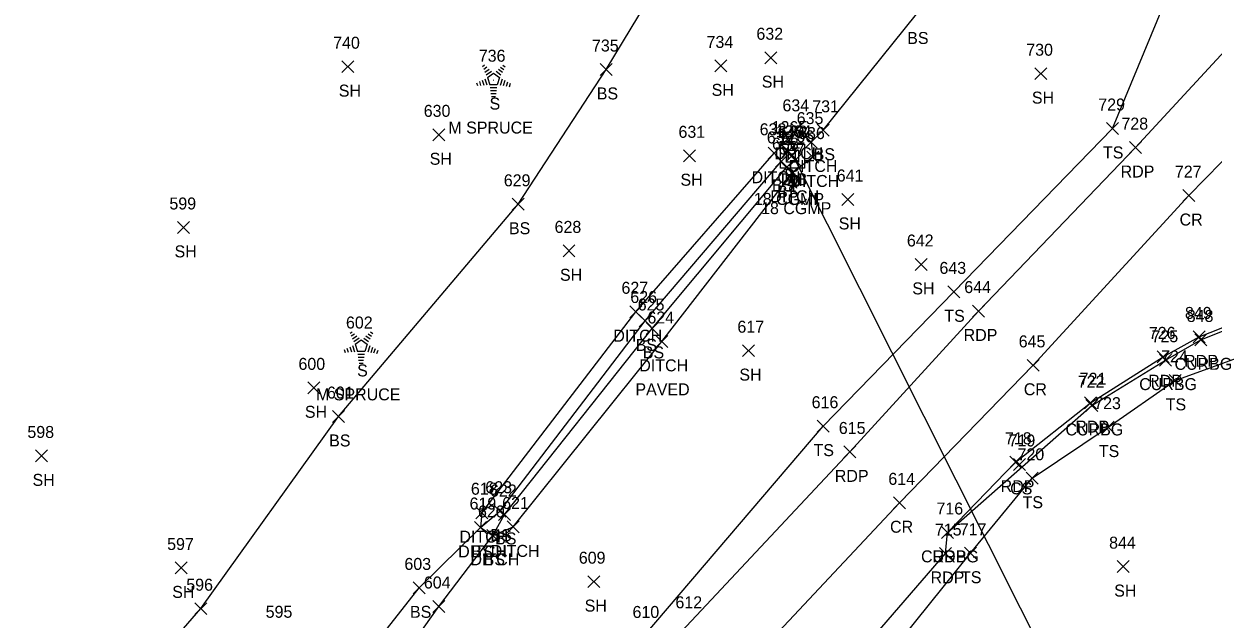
# Model space of a CAD drawing. Extents: x 1688195 to 1692013, y 424605 to 441234.
# Drawn here: x 1691519.2 to 1691718.1, y 439174.5 to 439274 of the extents above; entities that cross this region are included whole.
import ezdxf

# ---------------------------------------------------------------- set-up
doc = ezdxf.new("R2010")
doc.units = 0
for name, color, linetype in [('D_A', 7, 'Continuous'), ('D_C', 7, 'Continuous'), ('D_I', 7, 'Continuous'), ('D_TIC', 7, 'Continuous'), ('DCP', 7, 'Continuous'), ('DD', 7, 'Continuous'), ('DS', 7, 'Continuous'), ('L_A', 7, 'Continuous'), ('L_C', 7, 'Continuous'), ('L_I', 7, 'Continuous'), ('L_TIC', 7, 'Continuous'), ('LELB', 7, 'Continuous'), ('LTC', 7, 'Continuous'), ('P_A', 7, 'Continuous'), ('P_I', 7, 'Continuous'), ('P_TIC', 7, 'Continuous'), ('PET', 7, 'Continuous'), ('PRC', 7, 'Continuous'), ('R_A', 7, 'Continuous'), ('R_I', 7, 'Continuous'), ('R_TIC', 7, 'Continuous'), ('RC', 7, 'Continuous')]:
    doc.layers.add(name, color=color, linetype=linetype)

msp = doc.modelspace()

# ---------------------------------------------------------------- linework, layer by layer
at = {"layer": 'D_TIC'}
for points in [[(1691647.47, 439255.34), (1691649.47, 439257.34)], [(1691649.47, 439255.34), (1691647.47, 439257.34)], [(1691649.85, 439253.21), (1691651.85, 439255.21)], [(1691651.85, 439253.21), (1691649.85, 439255.21)], [(1691643.66, 439251.34), (1691645.66, 439253.34)], [(1691645.66, 439251.34), (1691643.66, 439253.34)], [(1691645.99, 439251.71), (1691647.99, 439253.71)], [(1691647.99, 439251.71), (1691645.99, 439253.71)], [(1691646.66, 439250.99), (1691648.66, 439252.99)], [(1691648.66, 439250.99), (1691646.66, 439252.99)], [(1691647.19, 439250.17), (1691649.19, 439252.17)], [(1691649.19, 439250.17), (1691647.19, 439252.17)], [(1691650.14, 439250.71), (1691652.14, 439252.71)], [(1691652.14, 439250.71), (1691650.14, 439252.71)], [(1691646.8, 439248.15), (1691648.8, 439250.15)], [(1691648.8, 439248.15), (1691646.8, 439250.15)], [(1691646.8, 439248.15), (1691648.8, 439250.15)], [(1691648.8, 439248.15), (1691646.8, 439250.15)], [(1691620.56, 439224.87), (1691622.56, 439226.87)], [(1691622.56, 439224.87), (1691620.56, 439226.87)], [(1691624.9, 439219.91), (1691626.9, 439221.91)], [(1691626.9, 439219.91), (1691624.9, 439221.91)], [(1691594.83, 439191.31), (1691596.83, 439193.31)], [(1691596.83, 439191.31), (1691594.83, 439193.31)], [(1691594.83, 439191.31), (1691596.83, 439193.31)], [(1691596.83, 439191.31), (1691594.83, 439193.31)], [(1691594.61, 439188.84), (1691596.61, 439190.84)], [(1691596.61, 439188.84), (1691594.61, 439190.84)], [(1691596.67, 439187.52), (1691598.67, 439189.52)], [(1691598.67, 439187.52), (1691596.67, 439189.52)], [(1691600.05, 439188.93), (1691602.05, 439190.93)], [(1691602.05, 439188.93), (1691600.05, 439190.93)]]:
    msp.add_lwpolyline(points, dxfattribs=at)
at = {"layer": 'DCP'}
msp.add_lwpolyline([(1691648.19, 439251.17), (1691707.28, 439133.69)], dxfattribs=at)
at = {"layer": 'DD'}
for points in [[(1691595.83, 439192.31), (1691621.56, 439225.87), (1691644.66, 439252.34), (1691648.47, 439256.34), (1691650.85, 439254.21), (1691651.14, 439251.71), (1691647.8, 439249.15)], [(1691595.83, 439192.31), (1691595.61, 439189.84), (1691597.67, 439188.52), (1691601.05, 439189.93), (1691625.9, 439220.91), (1691647.8, 439249.15)]]:
    msp.add_lwpolyline(points, dxfattribs=at)
at = {"layer": 'DS'}
for p, q in [((1691645.74, 439253.87), (1691649.74, 439253.87)), ((1691645.74, 439249.87), (1691645.74, 439253.87)), ((1691646.74, 439250.87), (1691646.74, 439252.87)), ((1691646.74, 439252.87), (1691648.74, 439252.87)), ((1691648.74, 439252.87), (1691648.74, 439250.87)), ((1691649.74, 439253.87), (1691649.74, 439249.87)), ((1691648.74, 439250.87), (1691646.74, 439250.87)), ((1691647.74, 439251.87), (1691647.74, 439251.87)), ((1691647.74, 439251.87), (1691647.74, 439251.87)), ((1691649.74, 439249.87), (1691645.74, 439249.87))]:
    msp.add_line(p, q, dxfattribs=at)
at = {"layer": 'L_TIC'}
for points in [[(1691643.12, 439267.3), (1691645.12, 439269.3)], [(1691645.12, 439267.3), (1691643.12, 439269.3)], [(1691572.41, 439265.8), (1691574.41, 439267.8)], [(1691574.41, 439265.8), (1691572.41, 439267.8)], [(1691615.58, 439265.33), (1691617.58, 439267.33)], [(1691617.58, 439265.33), (1691615.58, 439267.33)], [(1691634.74, 439265.93), (1691636.74, 439267.93)], [(1691636.74, 439265.93), (1691634.74, 439267.93)], [(1691688.26, 439264.63), (1691690.26, 439266.63)], [(1691690.26, 439264.63), (1691688.26, 439266.63)], [(1691651.84, 439255.18), (1691653.84, 439257.18)], [(1691653.84, 439255.18), (1691651.84, 439257.18)], [(1691700.22, 439255.48), (1691702.22, 439257.48)], [(1691702.22, 439255.48), (1691700.22, 439257.48)], [(1691587.6, 439254.42), (1691589.6, 439256.42)], [(1691589.6, 439254.42), (1691587.6, 439256.42)], [(1691629.52, 439250.92), (1691631.52, 439252.92)], [(1691631.52, 439250.92), (1691629.52, 439252.92)], [(1691644.87, 439249.99), (1691646.87, 439251.99)], [(1691646.87, 439249.99), (1691644.87, 439251.99)], [(1691644.87, 439249.99), (1691646.87, 439251.99)], [(1691646.87, 439249.99), (1691644.87, 439251.99)], [(1691645.72, 439248.94), (1691647.72, 439250.94)], [(1691647.72, 439248.94), (1691645.72, 439250.94)], [(1691655.97, 439243.62), (1691657.97, 439245.62)], [(1691657.97, 439243.62), (1691655.97, 439245.62)], [(1691600.9, 439242.82), (1691602.9, 439244.82)], [(1691602.9, 439242.82), (1691600.9, 439244.82)], [(1691544.96, 439238.95), (1691546.96, 439240.95)], [(1691546.96, 439238.95), (1691544.96, 439240.95)], [(1691609.38, 439235.04), (1691611.38, 439237.04)], [(1691611.38, 439235.04), (1691609.38, 439237.04)], [(1691668.27, 439232.77), (1691670.27, 439234.77)], [(1691670.27, 439232.77), (1691668.27, 439234.77)], [(1691673.71, 439228.19), (1691675.71, 439230.19)], [(1691675.71, 439228.19), (1691673.71, 439230.19)], [(1691622.09, 439223.33), (1691624.09, 439225.33)], [(1691624.09, 439223.33), (1691622.09, 439225.33)], [(1691623.28, 439222.08), (1691625.28, 439224.08)], [(1691625.28, 439222.08), (1691623.28, 439224.08)], [(1691639.37, 439218.37), (1691641.37, 439220.37)], [(1691641.37, 439218.37), (1691639.37, 439220.37)], [(1691710.71, 439213.4), (1691712.71, 439215.4)], [(1691712.71, 439213.4), (1691710.71, 439215.4)], [(1691566.74, 439212.16), (1691568.74, 439214.16)], [(1691568.74, 439212.16), (1691566.74, 439214.16)], [(1691570.85, 439207.37), (1691572.85, 439209.37)], [(1691572.85, 439207.37), (1691570.85, 439209.37)], [(1691651.84, 439205.76), (1691653.84, 439207.76)], [(1691653.84, 439205.76), (1691651.84, 439207.76)], [(1691699.53, 439205.6), (1691701.53, 439207.6)], [(1691701.53, 439205.6), (1691699.53, 439207.6)], [(1691521.22, 439200.79), (1691523.22, 439202.79)], [(1691523.22, 439200.79), (1691521.22, 439202.79)], [(1691684.67, 439199.37), (1691686.67, 439201.37)], [(1691686.67, 439199.37), (1691684.67, 439201.37)], [(1691686.79, 439197.06), (1691688.79, 439199.06)], [(1691688.79, 439197.06), (1691686.79, 439199.06)], [(1691597.8, 439191.56), (1691599.8, 439193.56)], [(1691599.8, 439191.56), (1691597.8, 439193.56)], [(1691598.59, 439191.01), (1691600.59, 439193.01)], [(1691600.59, 439191.01), (1691598.59, 439193.01)], [(1691594.61, 439188.84), (1691596.61, 439190.84)], [(1691596.61, 439188.84), (1691594.61, 439190.84)], [(1691596.67, 439187.52), (1691598.67, 439189.52)], [(1691598.67, 439187.52), (1691596.67, 439189.52)], [(1691676.5, 439184.53), (1691678.5, 439186.53)], [(1691678.5, 439184.53), (1691676.5, 439186.53)], [(1691544.57, 439182.08), (1691546.57, 439184.08)], [(1691546.57, 439182.08), (1691544.57, 439184.08)], [(1691702.02, 439182.3), (1691704.02, 439184.3)], [(1691704.02, 439182.3), (1691702.02, 439184.3)], [(1691613.52, 439179.79), (1691615.52, 439181.79)], [(1691615.52, 439179.79), (1691613.52, 439181.79)], [(1691584.36, 439178.75), (1691586.36, 439180.75)], [(1691586.36, 439178.75), (1691584.36, 439180.75)], [(1691547.83, 439175.28), (1691549.83, 439177.28)], [(1691549.83, 439175.28), (1691547.83, 439177.28)], [(1691587.61, 439175.65), (1691589.61, 439177.65)], [(1691589.61, 439175.65), (1691587.61, 439177.65)]]:
    msp.add_lwpolyline(points, dxfattribs=at)
at = {"layer": 'LELB'}
for points in [[(1691372.73, 438902.64), (1691398.57, 438929.63), (1691421.61, 438954.81), (1691450.5, 438984.08), (1691477.46, 439013.34), (1691508.26, 439046.52), (1691540.85, 439082.44), (1691568.31, 439110.72), (1691593.69, 439141.21), (1691622.93, 439171.73), (1691652.84, 439206.76), (1691674.71, 439229.19), (1691701.22, 439256.48), (1691710.89, 439279.75), (1691723.95, 439307.99), (1691712.17, 439332.07), (1691693.94, 439358.26), (1691684, 439373.02)], [(1691525.69, 439149.58), (1691548.83, 439176.28), (1691571.85, 439208.37), (1691601.9, 439243.82), (1691616.58, 439266.33), (1691638.43, 439302.46), (1691663.4, 439335.24), (1691663.94, 439360.51)], [(1691652.84, 439256.18), (1691668.47, 439275.59), (1691689.85, 439296.94)], [(1691358.65, 438915.95), (1691383.88, 438942.54), (1691406.19, 438968.83), (1691432.09, 439000.43), (1691458.78, 439030.79), (1691488.91, 439063.66), (1691516.55, 439102.83), (1691546.52, 439127.21), (1691571.44, 439162.09), (1691585.36, 439179.75), (1691595.61, 439189.84), (1691598.8, 439192.56), (1691623.09, 439224.33), (1691645.87, 439250.99)], [(1691362.51, 438912.64), (1691386.93, 438940.67), (1691409.23, 438967.09), (1691436.47, 438996.99), (1691463, 439026.81), (1691492.43, 439060.22), (1691523.16, 439097.82), (1691549.35, 439125.66), (1691575.52, 439158.24), (1691588.61, 439176.65), (1691597.67, 439188.52), (1691599.59, 439192.01), (1691624.28, 439223.08), (1691646.72, 439249.94), (1691645.87, 439250.99)], [(1691494.97, 438989.23), (1691529.39, 439026.47), (1691563.11, 439061.46), (1691592.32, 439093.25), (1691622.45, 439123.57), (1691640.28, 439144.55), (1691642.63, 439146.18), (1691644.54, 439148.64), (1691657.14, 439160.25), (1691677.5, 439185.53), (1691687.79, 439198.06), (1691700.53, 439206.6), (1691711.71, 439214.4), (1691729.93, 439221), (1691765.22, 439228.65), (1691785.8, 439230.06)]]:
    msp.add_lwpolyline(points, dxfattribs=at)
at = {"layer": 'LTC'}
for p, q in [((1691595.91, 439266.83), (1691596.27, 439267.09)), ((1691596.12, 439266.37), (1691596.65, 439266.75)), ((1691598.94, 439266.73), (1691599.49, 439266.33)), ((1691599.31, 439267.07), (1691599.73, 439266.77)), ((1691596.31, 439264.76), (1691596.64, 439263.74)), ((1691596.33, 439265.9), (1691597.03, 439266.41)), ((1691596.54, 439265.44), (1691597.42, 439266.07)), ((1691596.77, 439264.98), (1691597.78, 439265.72)), ((1691596.77, 439264.98), (1691597.15, 439263.79)), ((1691597.78, 439265.72), (1691598.77, 439264.99)), ((1691598.2, 439266.03), (1691599.01, 439265.44)), ((1691598.77, 439264.99), (1691598.38, 439263.79)), ((1691598.57, 439266.38), (1691599.25, 439265.88)), ((1691599.21, 439264.72), (1691598.87, 439263.68)), ((1691594.94, 439264.11), (1691595.1, 439263.65)), ((1691595.4, 439264.33), (1691595.61, 439263.68)), ((1691595.86, 439264.55), (1691596.13, 439263.71)), ((1691598.38, 439263.79), (1691597.15, 439263.79)), ((1691598.34, 439263.29), (1691597.2, 439263.29)), ((1691598.26, 439262.79), (1691597.27, 439262.79)), ((1691599.66, 439264.47), (1691599.37, 439263.59)), ((1691600.1, 439264.22), (1691599.86, 439263.49)), ((1691600.54, 439263.97), (1691600.36, 439263.4)), ((1691598.18, 439262.29), (1691597.34, 439262.29)), ((1691598.09, 439261.79), (1691597.42, 439261.79)), ((1691573.78, 439222.28), (1691574.14, 439222.54)), ((1691573.99, 439221.82), (1691574.52, 439222.2)), ((1691574.2, 439221.35), (1691574.9, 439221.86)), ((1691574.41, 439220.88), (1691575.29, 439221.52)), ((1691574.63, 439220.43), (1691575.65, 439221.16)), ((1691575.65, 439221.16), (1691576.64, 439220.44)), ((1691576.07, 439221.48), (1691576.88, 439220.89)), ((1691576.44, 439221.82), (1691577.12, 439221.33)), ((1691576.81, 439222.17), (1691577.36, 439221.77)), ((1691577.18, 439222.52), (1691577.6, 439222.22)), ((1691572.81, 439219.56), (1691572.97, 439219.09)), ((1691573.27, 439219.78), (1691573.48, 439219.12)), ((1691573.72, 439219.99), (1691574, 439219.16)), ((1691574.18, 439220.21), (1691574.51, 439219.19)), ((1691574.63, 439220.43), (1691575.02, 439219.24)), ((1691576.25, 439219.24), (1691575.02, 439219.24)), ((1691576.64, 439220.44), (1691576.25, 439219.24)), ((1691577.08, 439220.17), (1691576.74, 439219.13)), ((1691577.52, 439219.92), (1691577.24, 439219.03)), ((1691577.97, 439219.67), (1691577.73, 439218.94)), ((1691578.41, 439219.42), (1691578.23, 439218.84)), ((1691576.21, 439218.74), (1691575.07, 439218.74)), ((1691576.13, 439218.24), (1691575.14, 439218.24)), ((1691576.05, 439217.74), (1691575.21, 439217.74)), ((1691575.96, 439217.24), (1691575.29, 439217.24))]:
    msp.add_line(p, q, dxfattribs=at)
at = {"layer": 'P_TIC'}
for points in [[(1691704.09, 439252.29), (1691706.09, 439254.29)], [(1691706.09, 439252.29), (1691704.09, 439254.29)], [(1691713.01, 439244.27), (1691715.01, 439246.27)], [(1691715.01, 439244.27), (1691713.01, 439246.27)], [(1691677.85, 439224.99), (1691679.85, 439226.99)], [(1691679.85, 439224.99), (1691677.85, 439226.99)], [(1691714.71, 439220.67), (1691716.71, 439222.67)], [(1691716.71, 439220.67), (1691714.71, 439222.67)], [(1691708.71, 439217.34), (1691710.71, 439219.34)], [(1691710.71, 439217.34), (1691708.71, 439219.34)], [(1691686.96, 439215.92), (1691688.96, 439217.92)], [(1691688.96, 439215.92), (1691686.96, 439217.92)], [(1691696.53, 439209.68), (1691698.53, 439211.68)], [(1691698.53, 439209.68), (1691696.53, 439211.68)], [(1691656.32, 439201.46), (1691658.32, 439203.46)], [(1691658.32, 439201.46), (1691656.32, 439203.46)], [(1691684.04, 439199.74), (1691686.04, 439201.74)], [(1691686.04, 439199.74), (1691684.04, 439201.74)], [(1691664.6, 439192.96), (1691666.6, 439194.96)], [(1691666.6, 439192.96), (1691664.6, 439194.96)], [(1691672.65, 439188.01), (1691674.65, 439190.01)], [(1691674.65, 439188.01), (1691672.65, 439190.01)], [(1691672.33, 439184.49), (1691674.33, 439186.49)], [(1691674.33, 439184.49), (1691672.33, 439186.49)]]:
    msp.add_lwpolyline(points, dxfattribs=at)
at = {"layer": 'PET'}
for points in [[(1691375.46, 438899.9), (1691401.5, 438927.23), (1691424.19, 438951.44), (1691479.53, 439011.25), (1691510.32, 439044.28), (1691543.27, 439079.53), (1691570.24, 439108.89), (1691596.97, 439137.86), (1691630.02, 439173.34), (1691657.32, 439202.46), (1691678.85, 439225.99), (1691705.09, 439253.29), (1691720.65, 439270.18), (1691741.75, 439292.31), (1691750.04, 439301.33), (1691750.82, 439305.81), (1691750.97, 439309.53)], [(1691527.98, 439028.02), (1691561.01, 439063.43), (1691590.68, 439095.16), (1691619.98, 439126.48), (1691638.57, 439146.32), (1691653.83, 439162.94), (1691673.33, 439185.49), (1691673.65, 439189.01), (1691685.04, 439200.74), (1691697.53, 439210.68), (1691709.71, 439218.34), (1691715.71, 439221.67), (1691737.08, 439230.06)]]:
    msp.add_lwpolyline(points, dxfattribs=at)
at = {"layer": 'PRC'}
msp.add_lwpolyline([(1691383.45, 438891.46), (1691410.11, 438918.45), (1691432.71, 438943.44), (1691460.69, 438973.59), (1691487.77, 439002.58), (1691519.39, 439036.11), (1691551.83, 439070.88), (1691579.21, 439100.29), (1691605.82, 439129.37), (1691637.88, 439164.38), (1691665.6, 439193.96), (1691687.96, 439216.92), (1691714.01, 439245.27), (1691730.35, 439261.96), (1691750.53, 439284.62), (1691763.38, 439297.71)], dxfattribs=at)
at = {"layer": 'R_TIC'}
for points in [[(1691715, 439220.17), (1691717, 439222.17)], [(1691717, 439220.17), (1691715, 439222.17)], [(1691709.11, 439216.78), (1691711.11, 439218.78)], [(1691711.11, 439216.78), (1691709.11, 439218.78)], [(1691696.78, 439209.21), (1691698.78, 439211.21)], [(1691698.78, 439209.21), (1691696.78, 439211.21)], [(1691672.65, 439188.01), (1691674.65, 439190.01)], [(1691674.65, 439188.01), (1691672.65, 439190.01)]]:
    msp.add_lwpolyline(points, dxfattribs=at)
at = {"layer": 'RC'}
msp.add_lwpolyline([(1691673.65, 439189.01), (1691697.78, 439210.21), (1691710.11, 439217.78), (1691716, 439221.17), (1691737.36, 439229.74), (1691750.14, 439233.54), (1691763.41, 439236.01), (1691779.91, 439237.57), (1691792.75, 439237.29), (1691801.61, 439236.31), (1691804.32, 439236.19)], dxfattribs=at)

# ---------------------------------------------------------------- texts
at = {"layer": 'D_A'}
for s, p in [('DITCH', (1691644.71, 439251.34)), ('DITCH', (1691647.08, 439249.21)), ('DITCH', (1691640.9, 439247.34)), ('DIB', (1691645.77, 439246.99)), ('P', (1691646.36, 439247.71)), ('DI', (1691646.8, 439246.87)), ('DITCH', (1691647.38, 439246.71)), ('P', (1691647.57, 439246.17)), ('DITCH', (1691644.03, 439244.15)), ('DITCH', (1691644.03, 439244.15)), ('DITCH', (1691617.79, 439220.87)), ('DITCH', (1691622.13, 439215.91)), ('DITCH', (1691592.06, 439187.31)), ('DITCH', (1691592.06, 439187.31)), ('DITCH', (1691591.85, 439184.84)), ('DITCH', (1691593.91, 439183.52)), ('DITCH', (1691597.29, 439184.93))]:
    msp.add_text(s, height=2, dxfattribs=at).set_placement(p)
at = {"layer": 'D_C'}
for s, p in [('18 CGMP', (1691641.28, 439243.71)), ('18 CGMP', (1691642.49, 439242.17)), ('PAVED', (1691621.48, 439211.91))]:
    msp.add_text(s, height=2, dxfattribs=at).set_placement(p)
at = {"layer": 'D_I'}
for s, p in [('634', (1691646.06, 439259.34)), ('635', (1691648.44, 439257.21)), ('633', (1691642.25, 439255.34)), ('1265', (1691644.25, 439255.71)), ('1264', (1691644.92, 439254.99)), ('640', (1691645.25, 439254.87)), ('1266', (1691645.4, 439254.17)), ('636', (1691648.68, 439254.71)), ('637', (1691645.39, 439252.15)), ('637', (1691645.39, 439252.15)), ('627', (1691619.15, 439228.87)), ('624', (1691623.49, 439223.91)), ('618', (1691593.98, 439195.31)), ('618', (1691593.98, 439195.31)), ('619', (1691593.76, 439192.84)), ('620', (1691595.17, 439191.52)), ('621', (1691599.21, 439192.93))]:
    msp.add_text(s, height=2, dxfattribs=at).set_placement(p)
at = {"layer": 'L_A'}
for s, p in [('BS', (1691666.91, 439270.59)), ('SH', (1691642.6, 439263.3)), ('SH', (1691571.9, 439261.8)), ('BS', (1691615.02, 439261.33)), ('SH', (1691634.22, 439261.93)), ('S', (1691597.1, 439259.63)), ('SH', (1691687.75, 439260.63)), ('BS', (1691651.28, 439251.18)), ('TS', (1691699.63, 439251.48)), ('SH', (1691587.09, 439250.42)), ('SH', (1691629.01, 439246.92)), ('BS', (1691644.31, 439245.99)), ('BS', (1691644.31, 439245.99)), ('BS', (1691645.16, 439244.94)), ('SH', (1691655.46, 439239.62)), ('BS', (1691600.34, 439238.82)), ('SH', (1691544.45, 439234.95)), ('SH', (1691608.87, 439231.04)), ('SH', (1691667.76, 439228.77)), ('TS', (1691673.12, 439224.19)), ('BS', (1691621.53, 439219.33)), ('BS', (1691622.72, 439218.08)), ('S', (1691574.97, 439215.07)), ('SH', (1691638.86, 439214.37)), ('TS', (1691710.12, 439209.4)), ('SH', (1691566.23, 439208.16)), ('BS', (1691570.29, 439203.37)), ('TS', (1691651.25, 439201.76)), ('TS', (1691698.94, 439201.6)), ('SH', (1691520.71, 439196.79)), ('CS', (1691684.11, 439195.37)), ('TS', (1691686.2, 439193.06)), ('BS', (1691597.24, 439187.56)), ('BS', (1691598.03, 439187.01)), ('BS', (1691594.06, 439184.84)), ('BS', (1691596.11, 439183.52)), ('TS', (1691675.9, 439180.53)), ('SH', (1691544.06, 439178.08)), ('SH', (1691701.51, 439178.3)), ('SH', (1691613, 439175.79)), ('BS', (1691583.8, 439174.75))]:
    msp.add_text(s, height=2, dxfattribs=at).set_placement(p)
at = {"layer": 'L_C'}
for p in [(1691590.22, 439255.63), (1691568.09, 439211.07)]:
    msp.add_text('M SPRUCE', height=2, dxfattribs=at).set_placement(p)
at = {"layer": 'L_I'}
for s, p in [('632', (1691641.71, 439271.3)), ('740', (1691570.96, 439269.8)), ('735', (1691614.22, 439269.33)), ('734', (1691633.37, 439269.93)), ('736', (1691595.3, 439267.63)), ('730', (1691686.81, 439268.63)), ('731', (1691651.04, 439259.18)), ('729', (1691698.85, 439259.48)), ('630', (1691586.1, 439258.42)), ('631', (1691628.68, 439254.92)), ('639', (1691643.45, 439253.99)), ('639', (1691643.45, 439253.99)), ('638', (1691644.31, 439252.94)), ('629', (1691599.48, 439246.82)), ('641', (1691655.13, 439247.62)), ('599', (1691543.59, 439242.95)), ('628', (1691607.97, 439239.04)), ('642', (1691666.86, 439236.77)), ('643', (1691672.3, 439232.19)), ('626', (1691620.63, 439227.33)), ('625', (1691621.87, 439226.08)), ('602', (1691573.1, 439223.07)), ('617', (1691638.53, 439222.37)), ('724', (1691709.35, 439217.4)), ('600', (1691565.16, 439216.16)), ('601', (1691569.92, 439211.37)), ('616', (1691650.94, 439209.76)), ('723', (1691698.17, 439209.6)), ('598', (1691519.85, 439204.79)), ('719', (1691683.86, 439203.37)), ('720', (1691685.35, 439201.06)), ('623', (1691596.39, 439195.56)), ('622', (1691597.18, 439195.01)), ('619', (1691593.76, 439192.84)), ('620', (1691595.17, 439191.52)), ('717', (1691675.7, 439188.53)), ('597', (1691543.21, 439186.08)), ('844', (1691700.66, 439186.3)), ('609', (1691612.02, 439183.79)), ('603', (1691582.87, 439182.75)), ('596', (1691546.41, 439179.28)), ('604', (1691586.12, 439179.65)), ('595', (1691559.68, 439174.76)), ('610', (1691621, 439174.73))]:
    msp.add_text(s, height=2, dxfattribs=at).set_placement(p)
at = {"layer": 'LTC'}
for p in [(1691597.66, 439264.73), (1691575.53, 439220.18)]:
    msp.add_text('.', height=1.04, rotation=270, dxfattribs=at).set_placement(p)
at = {"layer": 'P_A'}
for s, p in [('RDP', (1691702.58, 439248.29)), ('CR', (1691712.44, 439240.27)), ('RDP', (1691676.34, 439220.99)), ('RDP', (1691713.2, 439216.67)), ('RDP', (1691707.2, 439213.34)), ('CR', (1691686.4, 439211.92)), ('RDP', (1691695.02, 439205.68)), ('RDP', (1691654.81, 439197.46)), ('RDP', (1691682.53, 439195.74)), ('CR', (1691664.04, 439188.96)), ('RDP', (1691671.14, 439184.01)), ('RDP', (1691670.82, 439180.49))]:
    msp.add_text(s, height=2, dxfattribs=at).set_placement(p)
at = {"layer": 'P_I'}
for s, p in [('728', (1691702.72, 439256.29)), ('727', (1691711.65, 439248.27)), ('644', (1691676.45, 439228.99)), ('849', (1691713.34, 439224.67)), ('726', (1691707.3, 439221.34)), ('645', (1691685.55, 439219.92)), ('721', (1691695.74, 439213.68)), ('615', (1691655.48, 439205.46)), ('718', (1691683.25, 439203.74)), ('614', (1691663.76, 439196.96)), ('716', (1691671.8, 439192.01)), ('715', (1691671.54, 439188.49)), ('612', (1691628.17, 439176.34))]:
    msp.add_text(s, height=2, dxfattribs=at).set_placement(p)
at = {"layer": 'R_A'}
for p in [(1691711.59, 439216.17), (1691705.69, 439212.78), (1691693.37, 439205.21), (1691669.23, 439184.01)]:
    msp.add_text('CURBG', height=2, dxfattribs=at).set_placement(p)
at = {"layer": 'R_I'}
for s, p in [('848', (1691713.64, 439224.17)), ('725', (1691707.75, 439220.78)), ('722', (1691695.42, 439213.21)), ('716', (1691671.8, 439192.01))]:
    msp.add_text(s, height=2, dxfattribs=at).set_placement(p)

doc.saveas('drawing.dxf')
